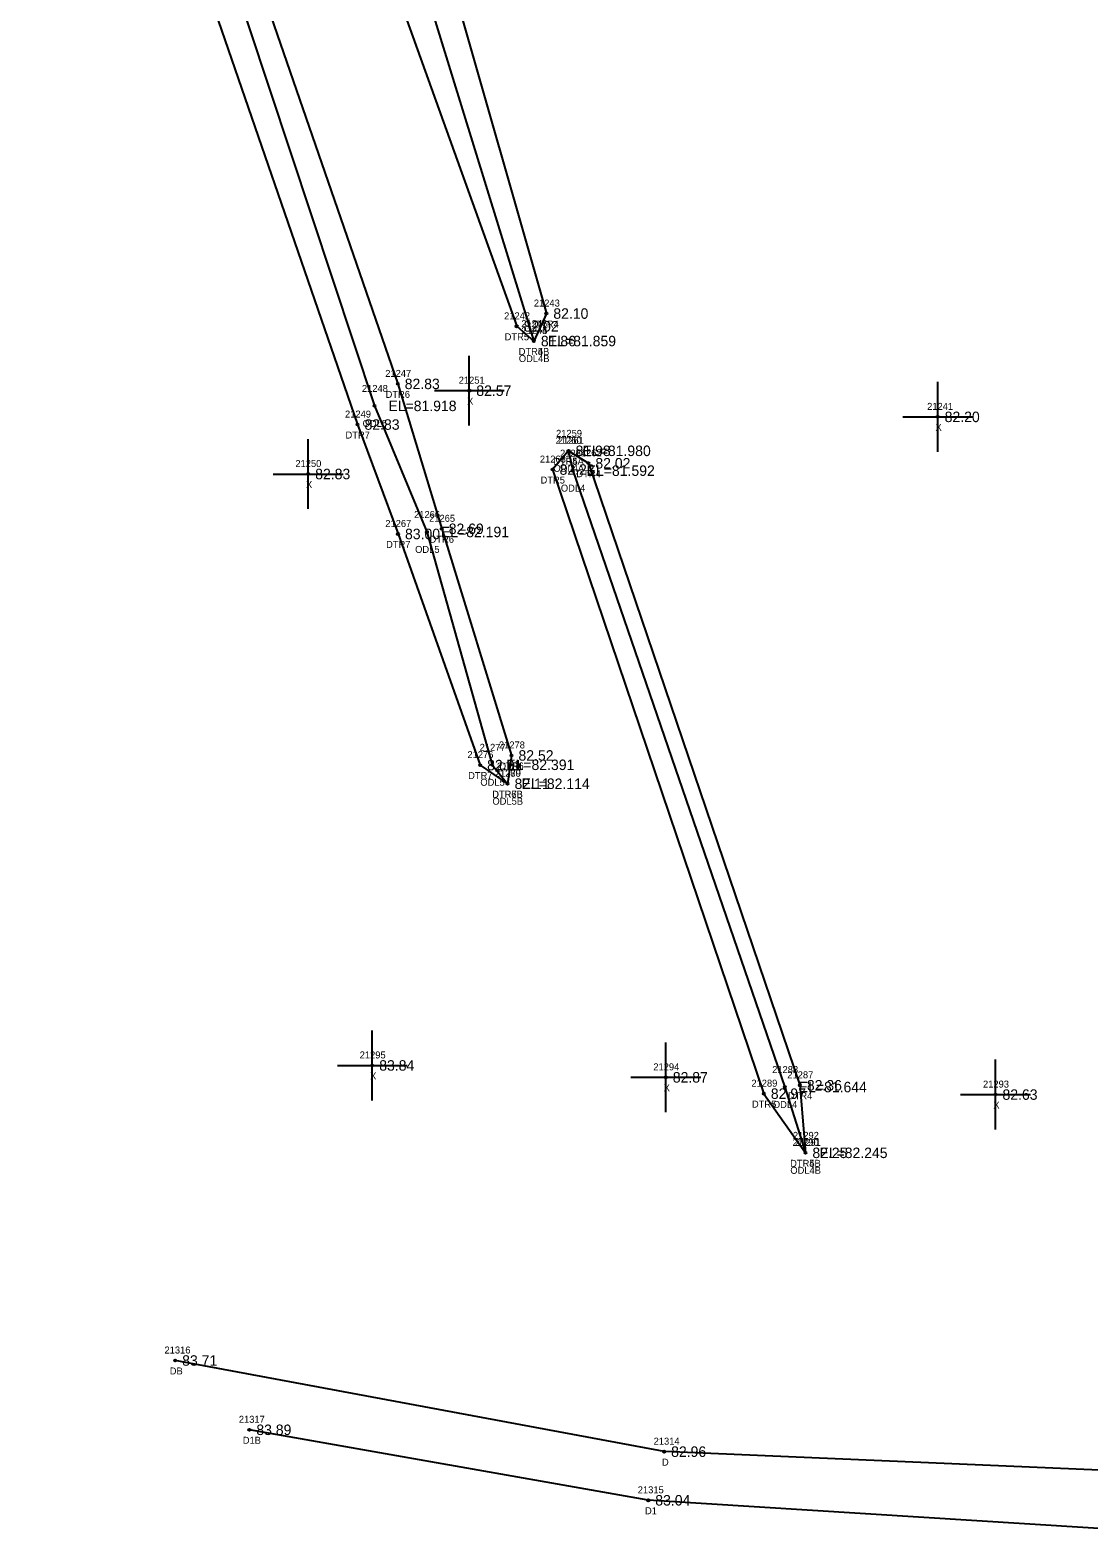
# Model space of a CAD drawing. Extents: x 2140110 to 2141565, y 506241 to 510327.
# Drawn here: x 2140403.2 to 2140554.8, y 507165.5 to 507381.3 of the extents above; entities that cross this region are included whole.
import ezdxf

# ---------------------------------------------------------------- set-up
doc = ezdxf.new("R2010")
doc.units = 0
for name, color, linetype in [('RD_EX_Driveway', 7, 'Continuous'), ('RD_EX_Driveway_txCode', 7, 'Continuous'), ('RD_EX_H2O', 7, 'Continuous'), ('RD_EX_H2O_txCode', 7, 'Continuous'), ('RD_EX_Misc', 7, 'Continuous'), ('RD_EX_Misc_txCode', 7, 'Continuous'), ('RD_EX_TX_Driveway_ELEV', 7, 'Continuous'), ('RD_EX_TX_H2O_ELEV', 7, 'Continuous'), ('RD_EX_TX_Misc_ELEV', 7, 'Continuous'), ('RD_SMD_Locator', 7, 'Continuous')]:
    doc.layers.add(name, color=color, linetype=linetype)

msp = doc.modelspace()

# ---------------------------------------------------------------- linework, layer by layer
at = {"layer": 'RD_EX_Driveway'}
for points in [[(2140577.5, 507174.26), (2140494.03, 507177.83), (2140424.01, 507190.88)], [(2140577.51, 507165.5), (2140491.76, 507170.87), (2140434.63, 507180.96)]]:
    msp.add_lwpolyline(points, dxfattribs=at)
at = {"layer": 'RD_EX_H2O'}
for points in [[(2140460.34, 507682.18), (2140426.85, 507538.87), (2140426.77, 507496.9), (2140443.77, 507422.13), (2140450.34, 507406.22), (2140456.51, 507384.59), (2140472.91, 507338.9), (2140475.38, 507336.79)], [(2140460.34, 507682.18), (2140466.97, 507681.89), (2140432.92, 507542.97), (2140432.5, 507498.67), (2140449.06, 507423.58), (2140455.82, 507407.99), (2140468.86, 507397.86), (2140469.47, 507392.25), (2140468.26, 507388.96), (2140463.58, 507388.34), (2140477.16, 507340.73), (2140475.38, 507336.79)], [(2140462.81, 507678.74), (2140430.15, 507541.27), (2140430.11, 507497.93), (2140446.41, 507422.64), (2140452.49, 507406.91), (2140455.52, 507397.77), (2140460.05, 507386.47), (2140475.38, 507336.79)], [(2140430.62, 507649.52), (2140427.22, 507648.51), (2140403.44, 507549.8), (2140403.24, 507488.1), (2140417.85, 507418.42), (2140450.12, 507324.84), (2140455.92, 507309.18), (2140467.68, 507276.1), (2140471.61, 507273.43)], [(2140430.62, 507649.52), (2140428.97, 507648.1), (2140406.43, 507549.61), (2140407.05, 507489.31), (2140422.46, 507418.23), (2140452.54, 507327.51), (2140460.06, 507309.47), (2140469.41, 507276.14), (2140471.61, 507273.43)], [(2140430.62, 507649.52), (2140430.5, 507648.1), (2140409.43, 507549.41), (2140409.91, 507490.22), (2140425.46, 507418.84), (2140455.88, 507330.66), (2140462.18, 507309.92), (2140472.17, 507277.48), (2140471.61, 507273.43)], [(2140480.35, 507321.08), (2140478.05, 507318.4), (2140508.31, 507229.07), (2140514.26, 507220.6)], [(2140480.35, 507321.08), (2140480.93, 507318.24), (2140511.3, 507230.02), (2140514.26, 507220.6)], [(2140480.35, 507321.08), (2140483.18, 507319.3), (2140513.47, 507230.27), (2140514.26, 507220.6)]]:
    msp.add_lwpolyline(points, dxfattribs=at)
at = {"layer": 'RD_EX_Misc'}
for p, q in [((2140466.13, 507324.69), (2140466.13, 507334.69)), ((2140533.2, 507320.94), (2140533.2, 507330.94)), ((2140461.13, 507329.69), (2140471.13, 507329.69)), ((2140528.2, 507325.94), (2140538.2, 507325.94)), ((2140443.06, 507312.76), (2140443.06, 507322.76)), ((2140438.06, 507317.76), (2140448.06, 507317.76)), ((2140452.23, 507228.11), (2140452.23, 507238.11)), ((2140494.27, 507226.41), (2140494.27, 507236.41)), ((2140541.48, 507223.94), (2140541.48, 507233.94)), ((2140447.23, 507233.11), (2140457.23, 507233.11)), ((2140489.27, 507231.41), (2140499.27, 507231.41)), ((2140536.48, 507228.94), (2140546.48, 507228.94))]:
    msp.add_line(p, q, dxfattribs=at)
at = {"layer": 'RD_SMD_Locator'}
for centre in [(2140472.91, 507338.9), (2140477.16, 507340.73), (2140475.38, 507336.79), (2140475.38, 507336.79), (2140475.38, 507336.79), (2140455.88, 507330.66), (2140466.13, 507329.69), (2140452.54, 507327.51), (2140533.2, 507325.94), (2140450.12, 507324.84), (2140480.35, 507321.08), (2140480.35, 507321.08), (2140480.35, 507321.08), (2140443.06, 507317.76), (2140478.05, 507318.4), (2140480.93, 507318.24), (2140483.18, 507319.3), (2140455.92, 507309.18), (2140460.06, 507309.47), (2140462.18, 507309.92), (2140472.17, 507277.48), (2140467.68, 507276.1), (2140469.41, 507276.14), (2140471.61, 507273.43), (2140471.61, 507273.43), (2140471.61, 507273.43), (2140452.23, 507233.11), (2140494.27, 507231.41), (2140508.31, 507229.07), (2140511.3, 507230.02), (2140513.47, 507230.27), (2140541.48, 507228.94), (2140514.26, 507220.6), (2140514.26, 507220.6), (2140514.26, 507220.6), (2140424.01, 507190.88), (2140434.63, 507180.96), (2140494.03, 507177.83), (2140491.76, 507170.87)]:
    msp.add_circle(centre, 0.15, dxfattribs=at)

# ---------------------------------------------------------------- texts
at = {"layer": 'RD_EX_Driveway_txCode'}
for s, p in [('21316', (2140422.48, 507191.88)), ('DB', (2140423.23, 507188.88)), ('21317', (2140433.12, 507181.96)), ('D1B', (2140433.69, 507178.96)), ('21314', (2140492.52, 507178.83)), ('D', (2140493.72, 507175.83)), ('21315', (2140490.25, 507171.87)), ('D1', (2140491.29, 507168.87))]:
    msp.add_text(s, height=1, dxfattribs=at).set_placement(p)
at = {"layer": 'RD_EX_H2O_txCode'}
for s, p in [('21243', (2140475.37, 507341.73)), ('21242', (2140471.11, 507339.9)), ('21246', (2140473.57, 507338.79)), ('DTR4', (2140475.45, 507338.73)), ('DTR5', (2140471.19, 507336.9)), ('21244', (2140473.59, 507337.79)), ('21245', (2140473.59, 507337.79)), ('ODL4B', (2140473.22, 507333.79)), ('DTR4B', (2140473.2, 507334.79)), ('DTR5B', (2140473.2, 507334.79)), ('21247', (2140454.09, 507331.66)), ('21248', (2140450.75, 507329.51)), ('DTR6', (2140454.14, 507328.66)), ('21249', (2140448.33, 507325.84)), ('DTR7', (2140448.4, 507322.84)), ('ODL5', (2140450.85, 507324.51)), ('21259', (2140478.55, 507323.08)), ('21260', (2140478.49, 507322.08)), ('21261', (2140478.81, 507322.08)), ('21263', (2140476.23, 507319.4)), ('DTR4A', (2140478.14, 507319.08)), ('DTR5A', (2140478.14, 507319.08)), ('21264', (2140479.12, 507320.24)), ('21262', (2140481.36, 507320.3)), ('DTR5', (2140476.33, 507316.4)), ('ODL4A', (2140478.17, 507318.08)), ('DTR4', (2140481.46, 507317.3)), ('ODL4', (2140479.24, 507315.24)), ('21267', (2140454.1, 507310.18)), ('21266', (2140458.22, 507311.47)), ('21265', (2140460.37, 507310.92)), ('DTR6', (2140460.44, 507307.92)), ('DTR7', (2140454.21, 507307.18)), ('ODL5', (2140458.37, 507306.47)), ('21277', (2140467.61, 507278.14)), ('21278', (2140470.37, 507278.48)), ('21276', (2140465.86, 507277.1)), ('21281', (2140470.09, 507275.43)), ('DTR6', (2140470.43, 507275.48)), ('DTR7', (2140465.96, 507274.1)), ('ODL5', (2140467.71, 507273.14)), ('21280', (2140469.77, 507274.43)), ('21279', (2140469.81, 507274.43)), ('DTR6B', (2140469.39, 507271.43)), ('DTR7B', (2140469.42, 507271.43)), ('ODL5B', (2140469.44, 507270.43)), ('21289', (2140506.52, 507230.07)), ('21288', (2140509.5, 507232.02)), ('21287', (2140511.67, 507231.27)), ('DTR4', (2140511.75, 507228.27)), ('DTR5', (2140506.6, 507227.07)), ('ODL4', (2140509.6, 507227.02)), ('21290', (2140512.43, 507221.6)), ('21292', (2140512.47, 507222.6)), ('21291', (2140512.75, 507221.6)), ('ODL4B', (2140512.1, 507217.6)), ('DTR5B', (2140512.07, 507218.6)), ('DTR4B', (2140512.07, 507218.6))]:
    msp.add_text(s, height=1, dxfattribs=at).set_placement(p)
at = {"layer": 'RD_EX_Misc_txCode'}
for s, p in [('21251', (2140464.61, 507330.69)), ('X', (2140465.81, 507327.69)), ('21241', (2140531.69, 507326.94)), ('X', (2140532.89, 507323.94)), ('21250', (2140441.22, 507318.76)), ('X', (2140442.74, 507315.76)), ('21295', (2140450.43, 507234.11)), ('21294', (2140492.48, 507232.41)), ('X', (2140451.92, 507231.11)), ('X', (2140493.96, 507229.41)), ('21293', (2140539.69, 507229.94)), ('X', (2140541.17, 507226.94))]:
    msp.add_text(s, height=1, dxfattribs=at).set_placement(p)
at = {"layer": 'RD_EX_TX_Driveway_ELEV'}
for s, p in [('83.71', (2140425.01, 507190.13)), ('83.89', (2140435.63, 507180.21)), ('82.96', (2140495.03, 507177.08)), ('83.04', (2140492.76, 507170.12))]:
    msp.add_text(s, height=1.5, dxfattribs=at).set_placement(p)
at = {"layer": 'RD_EX_TX_H2O_ELEV'}
for s, p in [('82.10', (2140478.16, 507339.98)), ('82.02', (2140473.91, 507338.15)), ('81.86', (2140476.38, 507336.04)), ('81.86', (2140476.38, 507336.04)), ('EL=81.859', (2140477.38, 507336.04)), ('82.83', (2140456.88, 507329.91)), ('EL=81.918', (2140454.54, 507326.76)), ('82.83', (2140451.12, 507324.09)), ('81.98', (2140481.35, 507320.33)), ('81.98', (2140481.35, 507320.33)), ('EL=81.980', (2140482.35, 507320.33)), ('82.02', (2140484.18, 507318.55)), ('82.23', (2140479.05, 507317.65)), ('EL=81.592', (2140482.93, 507317.49)), ('83.00', (2140456.92, 507308.43)), ('EL=82.191', (2140462.06, 507308.72)), ('82.69', (2140463.18, 507309.17)), ('82.91', (2140468.68, 507275.35)), ('EL=82.391', (2140471.41, 507275.39)), ('82.52', (2140473.17, 507276.73)), ('82.11', (2140472.61, 507272.68)), ('82.11', (2140472.61, 507272.68)), ('EL=82.114', (2140473.61, 507272.68)), ('82.36', (2140514.47, 507229.52)), ('82.97', (2140509.31, 507228.32)), ('EL=81.644', (2140513.3, 507229.27)), ('82.25', (2140515.26, 507219.85)), ('82.25', (2140515.26, 507219.85)), ('EL=82.245', (2140516.26, 507219.85))]:
    msp.add_text(s, height=1.5, dxfattribs=at).set_placement(p)
at = {"layer": 'RD_EX_TX_Misc_ELEV'}
for s, p in [('82.57', (2140467.13, 507328.94)), ('82.20', (2140534.2, 507325.19)), ('82.83', (2140444.06, 507317.01)), ('83.84', (2140453.23, 507232.36)), ('82.87', (2140495.27, 507230.66)), ('82.63', (2140542.48, 507228.19))]:
    msp.add_text(s, height=1.5, dxfattribs=at).set_placement(p)

doc.saveas('drawing.dxf')
